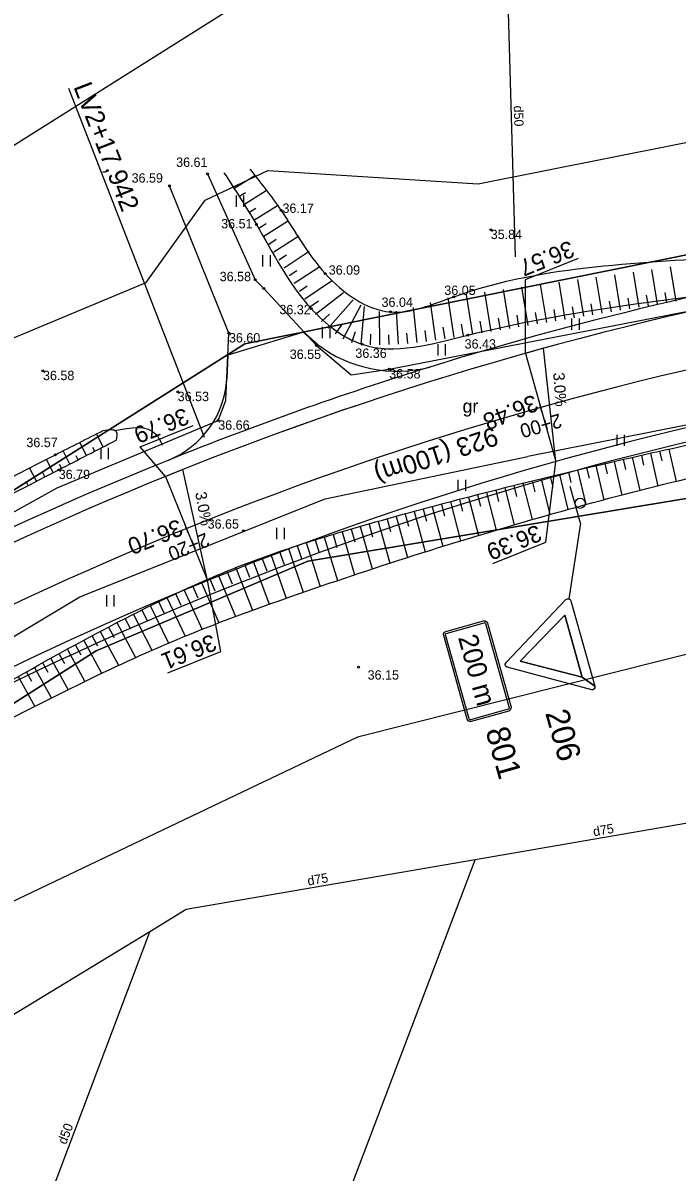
# Model space of a CAD drawing. Extents: x 469981 to 472086, y 246785 to 247785.
# Drawn here: x 471754 to 471788.9, y 247573.1 to 247634.5 of the extents above; entities that cross this region are included whole.
import ezdxf

# ---------------------------------------------------------------- set-up
doc = ezdxf.new("R2010")
doc.units = 0
for name, color, linetype in [('0_923', 7, 'Continuous'), ('0_Asfalta_mala', 7, 'Continuous'), ('0_Asfalta_Nomale', 7, 'Continuous'), ('0_Horiz_aprakst', 7, 'Continuous'), ('0_Ruut_Braukt', 7, 'Continuous'), ('0_Ruut_nomale', 7, 'Continuous'), ('0_Ruutojums_Nobrauktuves_pieslegumi', 7, 'Continuous'), ('0_vertikals', 7, 'Continuous'), ('0_vertkals_cipari', 7, 'Continuous'), ('0_Ziimes', 7, 'Continuous'), ('21', 7, 'Continuous'), ('5_patagas', 7, 'Continuous'), ('6_piketaza', 7, 'Continuous'), ('CELI_CMAL_####_####_#', 7, 'Continuous'), ('CELI_CSEG_####_TKST_#', 7, 'Continuous'), ('DREN_VADP_####_####_#', 7, 'Continuous'), ('DREN_VADP_####_TKST_#', 7, 'Continuous'), ('DREN_VADP_KLKT_####_#', 7, 'Continuous'), ('DREN_VADP_KLKT_TKST_#', 7, 'Continuous'), ('RAMI_UZMR_####_####_#', 7, 'Continuous'), ('RELJ_AATZ_####_TKST_#', 7, 'Continuous'), ('RELJ_ELEM_####_####_#', 7, 'Continuous'), ('RELJ_NOGA_####_####_#', 7, 'Continuous'), ('RELJ_NOGL_####_####_#', 7, 'Continuous'), ('ROBZ_IERR_####_####_#', 7, 'Continuous'), ('ROBZ_PROJ_####_####_#', 7, 'Continuous'), ('TERT_ELEM_####_####_#', 7, 'Continuous'), ('TERT_KONT_####_####_#', 7, 'Continuous')]:
    doc.layers.add(name, color=color, linetype=linetype)

msp = doc.modelspace()

# ---------------------------------------------------------------- linework, layer by layer
at = {"layer": '0_923'}
msp.add_arc((471830.321, 247440.673), 180, 99.00786, 123.42635, dxfattribs=at)
at = {"layer": '0_Asfalta_mala'}
for radius in [183, 177]:
    msp.add_arc((471830.321, 247440.673), radius, 99.00786, 123.42635, dxfattribs=at)
at = {"layer": '0_Asfalta_Nomale'}
for p, q in [((471768.971, 247617.989), (471764.929, 247616.759)), ((471768.971, 247617.989), (471769.697, 247617.337)), ((471764.929, 247616.759), (471764.874, 247615.489))]:
    msp.add_line(p, q, dxfattribs=at)
for centre, radius, start, end in [((471830.321, 247440.673), 183.75, 99.00786, 107.28848), ((471773.95, 247622.896), 7, 232.57724, 284.59006), ((471759.883, 247615.788), 5, 292.12547, 356.58033), ((471830.321, 247440.673), 176.25, 99.00786, 123.42635), ((471830.321, 247440.673), 183.75, 111.90633, 123.42635)]:
    msp.add_arc(centre, radius, start, end, dxfattribs=at)
at = {"layer": '0_Ruut_Braukt'}
for radius in [183, 177]:
    msp.add_arc((471830.321, 247440.673), radius, 99.00786, 123.42635, dxfattribs=at)
at = {"layer": '0_Ruut_nomale'}
for radius, start, end in [(183.75, 99.00786, 107.28848), (183, 99.00801, 123.42635), (183.75, 107.28848, 111.90633), (177, 99.00801, 123.42635), (176.25, 99.00786, 123.42635), (183.75, 111.90633, 123.42635)]:
    msp.add_arc((471830.321, 247440.673), radius, start, end, dxfattribs=at)
at = {"layer": '0_Ruutojums_Nobrauktuves_pieslegumi'}
for p, q in [((471768.971, 247617.989), (471764.929, 247616.759)), ((471769.697, 247617.337), (471768.971, 247617.989)), ((471764.929, 247616.759), (471764.874, 247615.489))]:
    msp.add_line(p, q, dxfattribs=at)
for centre, radius, start, end in [((471773.95, 247622.896), 7, 232.57724, 284.59006), ((471830.321, 247440.673), 183.75, 107.28848, 111.90633), ((471759.883, 247615.788), 5, 292.12547, 356.58033)]:
    msp.add_arc(centre, radius, start, end, dxfattribs=at)
at = {"layer": '0_vertikals'}
for p, q in [((471780.823, 247620.8), (471783.65, 247621.935)), ((471780.819, 247616.851), (471780.823, 247620.8)), ((471760.248, 247611.867), (471763.075, 247613.001)), ((471761.59, 247610.276), (471760.248, 247611.867)), ((471781.907, 247606.764), (471782.442, 247611.075)), ((471779.079, 247605.629), (471781.907, 247606.764)), ((471764.541, 247600.923), (471763.843, 247604.715)), ((471761.713, 247599.788), (471764.541, 247600.923))]:
    msp.add_line(p, q, dxfattribs=at)
for points in [[(471782.442, 247611.075), (471781.783, 247617.12), (471780.819, 247616.851)], [(471763.843, 247604.715), (471762.517, 247610.65), (471761.59, 247610.276)]]:
    msp.add_lwpolyline(points, close=True, dxfattribs=at)
at = {"layer": '0_Ziimes'}
for q in [(471783.2, 247609.739), (471783.134, 247603.747)]:
    msp.add_line((471783.75, 247607.782), q, dxfattribs=at)
for points in [[(471784.487, 247598.932), (471784.417, 247598.89), (471784.354, 247598.885), (471779.847, 247600.089), (471779.756, 247600.153), (471779.731, 247600.253), (471779.782, 247600.351), (471782.977, 247603.699), (471783.009, 247603.726), (471783.037, 247603.741), (471783.053, 247603.747), (471783.134, 247603.747), (471783.202, 247603.709), (471783.244, 247603.639), (471784.524, 247599.083), (471783.846, 247599.568), (471782.918, 247602.871), (471780.537, 247600.42), (471783.846, 247599.568), (471784.524, 247599.083), (471784.525, 247599)], [(471776.583, 247601.891), (471778.612, 247602.461), (471778.64, 247602.462), (471778.662, 247602.449), (471778.675, 247602.424), (471779.938, 247597.93), (471779.938, 247597.898), (471779.923, 247597.872), (471779.899, 247597.856), (471777.883, 247597.29), (471777.853, 247597.29), (471777.829, 247597.306), (471777.813, 247597.333), (471776.55, 247601.83), (471776.55, 247601.858), (471776.563, 247601.879)], [(471780.537, 247600.42), (471782.918, 247602.871), (471783.847, 247599.568)]]:
    msp.add_lwpolyline(points, close=True, dxfattribs=at)
for points in [[(471778.569, 247602.564), (471778.662, 247602.565), (471778.738, 247602.524), (471778.782, 247602.452), (471780.043, 247597.965), (471780.041, 247597.871), (471779.995, 247597.793), (471779.92, 247597.747), (471777.919, 247597.187), (471777.832, 247597.188), (471777.755, 247597.233), (471777.706, 247597.313), (471776.448, 247601.789), (471776.447, 247601.881), (471776.488, 247601.956), (471776.561, 247601.999), (471778.569, 247602.564)], [(471778.612, 247602.461), (471778.64, 247602.462), (471778.662, 247602.449), (471778.675, 247602.424), (471779.938, 247597.93), (471779.938, 247597.898), (471779.923, 247597.872), (471779.899, 247597.856), (471777.883, 247597.29), (471777.853, 247597.29), (471777.829, 247597.306), (471777.813, 247597.333), (471776.55, 247601.83), (471776.55, 247601.858), (471776.563, 247601.879), (471776.583, 247601.891), (471778.612, 247602.461)], [(471782.918, 247602.871), (471783.847, 247599.568), (471780.537, 247600.42), (471782.918, 247602.871)]]:
    msp.add_lwpolyline(points, dxfattribs=at)
msp.add_circle((471783.732, 247608.844), 0.27, dxfattribs=at)
at = {"layer": '21'}
msp.add_arc((471830.321, 247440.673), 180, 99.00786, 123.42635, dxfattribs=at)
at = {"layer": '5_patagas'}
msp.add_lwpolyline([(471763.671, 247612.355), (471756.433, 247631)], dxfattribs=at)
at = {"layer": '6_piketaza'}
for points in [[(471781.698, 247613.722), (471781.563, 247614.204)], [(471762.81, 247607.264), (471762.622, 247607.727)]]:
    msp.add_lwpolyline(points, dxfattribs=at)
at = {"layer": 'CELI_CMAL_####_####_#'}
for points in [[(471763.843, 247626.44), (471766.384, 247620.784), (471766.846, 247620.315), (471769.651, 247617.268), (471771.51, 247615.708), (471773.538, 247616.009), (471793.17, 247619.818), (471820.132, 247624.478), (471843.737, 247629.53), (471860.544, 247633.651)], [(471862.243, 247628.404), (471842.392, 247623.599), (471819.645, 247618.849), (471794.254, 247613.976), (471780.938, 247611.344)], [(471444.29, 247410.189), (471472.037, 247427.783), (471529.617, 247464.738), (471552.455, 247479.724), (471579.938, 247497.81), (471608.708, 247516.399), (471640.167, 247536.853), (471663.898, 247552.17), (471700.29, 247576.588), (471731.688, 247596.287), (471755.809, 247609.67), (471764.411, 247613.273), (471764.823, 247614.335), (471764.981, 247617.933), (471761.802, 247625.793)], [(471701.326, 247547.673), (471701.369, 247550.631), (471701.11, 247563.475), (471701.252, 247565.777), (471702.218, 247568.043), (471703.6, 247570.107), (471733.855, 247589.972), (471757.011, 247603.842), (471770.12, 247609.089), (471780.938, 247611.344)]]:
    msp.add_lwpolyline(points, dxfattribs=at)
at = {"layer": 'DREN_VADP_####_####_#'}
for points in [[(471617.262, 247542.218), (471779.627, 247644.425)], [(471779.627, 247644.425), (471780.269, 247621.999)], [(471769.353, 247566.672), (471778.135, 247589.816)], [(471750.407, 247558.597), (471760.751, 247585.97)]]:
    msp.add_lwpolyline(points, dxfattribs=at)
at = {"layer": 'DREN_VADP_KLKT_####_#'}
msp.add_lwpolyline([(471874.265, 247606.401), (471874.259, 247606.399), (471867.456, 247605.226), (471862.705, 247604.407), (471853.259, 247602.776), (471834.413, 247599.524), (471815.19, 247596.208), (471796.375, 247592.962), (471778.135, 247589.816), (471762.691, 247587.151), (471760.751, 247585.97), (471739.894, 247573.284), (471721.842, 247562.305), (471686.843, 247541.016), (471672.454, 247532.264), (471658.683, 247523.887), (471644.34, 247515.163), (471630.529, 247506.762), (471615.384, 247497.552), (471601.35, 247489.016), (471587.985, 247480.886)], dxfattribs=at)
at = {"layer": 'RAMI_UZMR_####_####_#'}
for points in [[(471355.9, 247363.1), (471457.4, 247429.3), (471524.252, 247472.902), (471743.701, 247613.609), (471760.558, 247620.637), (471763.718, 247625.03), (471767.054, 247626.612), (471778.292, 247625.909), (471806.563, 247631.532), (471842.307, 247641.196)], [(471848.639, 247612.324), (471820.308, 247604.26), (471796.252, 247602.503), (471771.845, 247596.352), (471738.658, 247580.538), (471704.768, 247555.586), (471706.876, 247550.666), (471698.447, 247548.03), (471696.867, 247547.678), (471692.126, 247547.503), (471681.941, 247541.88), (471585.706, 247481.922), (471472.95, 247409.108), (471442.347, 247392.641), (471399.385, 247364.445), (471380.292, 247353.371), (471352.036, 247335.759)]]:
    msp.add_lwpolyline(points, dxfattribs=at)
at = {"layer": 'RELJ_ELEM_####_####_#'}
for centre in [(471763.843, 247626.44), (471761.801, 247625.794), (471767.765, 247624.485), (471766.447, 247623.736), (471778.961, 247623.454), (471766.384, 247620.784), (471770.126, 247621.109), (471766.846, 247620.315), (471776.986, 247619.873), (471769.372, 247619.245), (471773.604, 247619.063), (471764.98, 247617.933), (471777.734, 247617.819), (471769.651, 247617.268), (471772.099, 247617.334), (471755.052, 247615.921), (471773.538, 247616.01), (471762.244, 247614.8), (471764.41, 247613.273), (471755.711, 247611.433), (471755.893, 247610.639), (471765.763, 247607.382), (471771.907, 247600.096)]:
    msp.add_circle(centre, 0.05, dxfattribs=at)
at = {"layer": 'RELJ_NOGA_####_####_#'}
for p, q in [((471764.716, 247626.497), (471764.716, 247626.498)), ((471765.247, 247625.65), (471766.359, 247626.347)), ((471764.981, 247626.074), (471764.982, 247626.074)), ((471765.513, 247625.226), (471765.857, 247625.443)), ((471765.778, 247624.803), (471766.964, 247625.546)), ((471766.044, 247624.379), (471766.411, 247624.609)), ((471766.31, 247623.956), (471767.569, 247624.745)), ((471766.576, 247623.532), (471766.964, 247623.776)), ((471766.842, 247623.109), (471768.159, 247623.943)), ((471767.111, 247622.687), (471767.509, 247622.942)), ((471767.38, 247622.266), (471768.716, 247623.124)), ((471767.651, 247621.846), (471768.053, 247622.105)), ((471767.923, 247621.426), (471769.267, 247622.3)), ((471768.471, 247620.59), (471769.835, 247621.493)), ((471787.872, 247619.472), (471787.568, 247621.33)), ((471788.859, 247619.633), (471788.557, 247621.477)), ((471768.196, 247621.008), (471768.602, 247621.274)), ((471769.026, 247619.758), (471770.454, 247620.718)), ((471783.924, 247618.828), (471783.605, 247620.786)), ((471784.911, 247618.988), (471784.596, 247620.919)), ((471785.898, 247619.149), (471785.588, 247621.052)), ((471786.885, 247619.311), (471786.578, 247621.189)), ((471768.748, 247620.174), (471769.164, 247620.451)), ((471769.596, 247618.937), (471771.092, 247620.095)), ((471778.989, 247618.024), (471778.648, 247620.116)), ((471779.976, 247618.184), (471779.639, 247620.254)), ((471780.963, 247618.345), (471780.63, 247620.387)), ((471781.95, 247618.506), (471781.622, 247620.52)), ((471782.937, 247618.667), (471782.613, 247620.653)), ((471788.365, 247619.553), (471788.275, 247620.108)), ((471769.305, 247619.343), (471769.755, 247619.648)), ((471770.274, 247618.203), (471771.611, 247619.7)), ((471776.026, 247617.556), (471775.75, 247619.574)), ((471777.015, 247617.703), (471776.682, 247619.819)), ((471778.002, 247617.863), (471777.658, 247619.973)), ((471784.418, 247618.908), (471784.323, 247619.491)), ((471785.405, 247619.069), (471785.311, 247619.644)), ((471786.392, 247619.23), (471786.299, 247619.797)), ((471787.378, 247619.391), (471787.287, 247619.951)), ((471769.918, 247618.555), (471770.352, 247618.951)), ((471771.089, 247617.629), (471772.044, 247619.44)), ((471772.039, 247617.338), (471772.226, 247619.35)), ((471773.038, 247617.309), (471773.024, 247619.094)), ((471774.038, 247617.345), (471773.929, 247619.099)), ((471775.034, 247617.432), (471774.836, 247619.3)), ((471780.47, 247618.265), (471780.369, 247618.882)), ((471781.457, 247618.426), (471781.357, 247619.034)), ((471782.444, 247618.586), (471782.346, 247619.186)), ((471783.431, 247618.747), (471783.334, 247619.339)), ((471770.663, 247617.89), (471771.02, 247618.388)), ((471776.521, 247617.627), (471776.427, 247618.251)), ((471777.509, 247617.782), (471777.406, 247618.418)), ((471778.496, 247617.943), (471778.393, 247618.574)), ((471779.483, 247618.104), (471779.381, 247618.728)), ((471771.55, 247617.437), (471771.733, 247618.02)), ((471772.538, 247617.314), (471772.553, 247617.881)), ((471773.538, 247617.32), (471773.52, 247617.841)), ((471774.536, 247617.383), (471774.488, 247617.923)), ((471775.53, 247617.49), (471775.458, 247618.073)), ((471758.264, 247611.851), (471757.909, 247612.546)), ((471756.484, 247610.94), (471756.124, 247611.642)), ((471757.374, 247611.396), (471757.016, 247612.094)), ((471757.819, 247611.623), (471757.712, 247611.832)), ((471758.709, 247612.079), (471758.709, 247612.079)), ((471787.493, 247611.526), (471787.887, 247609.766)), ((471787.981, 247611.635), (471788.098, 247611.11)), ((471788.469, 247611.743), (471788.854, 247610.002)), ((471755.594, 247610.484), (471755.232, 247611.19)), ((471756.039, 247610.712), (471755.93, 247610.924)), ((471756.929, 247611.168), (471756.821, 247611.378)), ((471785.056, 247610.968), (471785.183, 247610.424)), ((471785.543, 247611.081), (471785.96, 247609.28)), ((471786.03, 247611.194), (471786.154, 247610.657)), ((471786.518, 247611.305), (471786.923, 247609.526)), ((471787.005, 247611.416), (471787.125, 247610.885)), ((471754.704, 247610.027), (471754.339, 247610.735)), ((471755.149, 247610.256), (471755.04, 247610.468)), ((471782.138, 247610.272), (471782.277, 247609.704)), ((471782.624, 247610.39), (471783.078, 247608.511)), ((471783.11, 247610.507), (471783.244, 247609.948)), ((471783.596, 247610.624), (471784.039, 247608.773)), ((471784.083, 247610.739), (471784.213, 247610.188)), ((471784.569, 247610.854), (471785, 247609.029)), ((471754.26, 247609.797), (471754.15, 247610.01)), ((471779.712, 247609.669), (471780.21, 247607.698)), ((471780.197, 247609.791), (471780.344, 247609.205)), ((471780.682, 247609.912), (471781.165, 247607.974)), ((471781.167, 247610.033), (471781.31, 247609.456)), ((471781.652, 247610.153), (471782.122, 247608.245)), ((471777.291, 247609.045), (471777.453, 247608.428)), ((471777.775, 247609.171), (471778.305, 247607.133)), ((471778.259, 247609.297), (471778.415, 247608.69)), ((471778.743, 247609.422), (471779.256, 247607.418)), ((471779.227, 247609.545), (471779.379, 247608.949)), ((471775.358, 247608.531), (471775.53, 247607.892)), ((471775.841, 247608.661), (471776.407, 247606.551)), ((471776.324, 247608.789), (471776.491, 247608.162)), ((471776.808, 247608.917), (471777.355, 247606.844)), ((471772.947, 247607.87), (471773.567, 247605.647)), ((471773.429, 247608.004), (471773.612, 247607.343)), ((471773.911, 247608.137), (471774.513, 247605.952)), ((471774.393, 247608.269), (471774.571, 247607.619)), ((471774.876, 247608.4), (471775.457, 247606.253)), ((471771.022, 247607.326), (471771.68, 247605.024)), ((471771.503, 247607.463), (471771.698, 247606.779)), ((471771.984, 247607.6), (471772.624, 247605.338)), ((471772.466, 247607.735), (471772.654, 247607.062)), ((471768.633, 247606.592), (471768.864, 247605.89)), ((471769.108, 247606.747), (471769.858, 247604.408)), ((471769.585, 247606.897), (471769.804, 247606.197)), ((471770.063, 247607.044), (471770.772, 247604.719)), ((471770.542, 247607.187), (471770.746, 247606.492)), ((471767.214, 247606.106), (471768.04, 247603.779)), ((471767.685, 247606.272), (471767.928, 247605.572)), ((471768.159, 247606.434), (471768.951, 247604.096)), ((471765.341, 247605.405), (471766.236, 247603.134)), ((471765.807, 247605.586), (471766.071, 247604.899)), ((471766.274, 247605.763), (471767.138, 247603.459)), ((471766.743, 247605.937), (471766.997, 247605.242)), ((471763.952, 247604.839), (471764.232, 247604.177)), ((471764.413, 247605.032), (471765.337, 247602.801)), ((471764.876, 247605.22), (471765.148, 247604.544)), ((471762.577, 247604.239), (471763.544, 247602.112)), ((471763.034, 247604.443), (471763.32, 247603.796)), ((471763.492, 247604.643), (471764.437, 247602.46)), ((471761.218, 247603.604), (471761.512, 247602.994)), ((471761.669, 247603.82), (471762.644, 247601.751)), ((471762.122, 247604.031), (471762.412, 247603.401)), ((471759.875, 247602.936), (471760.869, 247601.005)), ((471760.321, 247603.163), (471760.618, 247602.572)), ((471760.768, 247603.385), (471761.753, 247601.383)), ((471758.99, 247602.471), (471759.985, 247600.614)), ((471759.431, 247602.705), (471759.729, 247602.137)), ((471757.671, 247601.756), (471757.961, 247601.226)), ((471758.111, 247601.995), (471759.085, 247600.202)), ((471758.55, 247602.233), (471758.847, 247601.687)), ((471756.794, 247601.276), (471757.077, 247600.76)), ((471757.233, 247601.516), (471758.184, 247599.773)), ((471755.479, 247600.555), (471756.397, 247598.886)), ((471755.917, 247600.796), (471756.195, 247600.29)), ((471756.355, 247601.036), (471757.29, 247599.332)), ((471754.603, 247600.072), (471755.505, 247598.439)), ((471755.041, 247600.314), (471755.314, 247599.819)), ((471753.728, 247599.588), (471754.613, 247597.99)), ((471754.165, 247599.831), (471754.433, 247599.346))]:
    msp.add_line(p, q, dxfattribs=at)
for points in [[(471764.716, 247626.497), (471766.448, 247623.736), (471769.372, 247619.245), (471772.099, 247617.333), (471777.734, 247617.819), (471792.871, 247620.291), (471820.146, 247624.816), (471854.894, 247634.06), (471858.623, 247635.133)], [(471706.609, 247571.244), (471711.797, 247574.654), (471722.947, 247581.604), (471728.593, 247584.967), (471734.238, 247588.334), (471740.292, 247591.93), (471746.383, 247595.455), (471752.516, 247598.916), (471758.702, 247602.316), (471764.709, 247605.153), (471767.819, 247606.318), (471770.991, 247607.318), (471782.736, 247610.417), (471794.579, 247613.027), (471800.844, 247614.22), (471807.118, 247615.36), (471813.386, 247616.524), (471819.633, 247617.79), (471842.376, 247622.859), (471856.937, 247625.885), (471859.609, 247626.582), (471862.301, 247626.993)], [(471341.934, 247360.736), (471344.51, 247356.259), (471349.946, 247353.745), (471355.895, 247354.991), (471376.693, 247368.011), (471396.058, 247380.323), (471444.047, 247411.052), (471471.484, 247428.432), (471497.591, 247445.096), (471529.061, 247465.658), (471552.024, 247480.39), (471579.849, 247498.336), (471608.29, 247516.955), (471640.013, 247537.434), (471663.526, 247552.835), (471700.309, 247577.155), (471731.58, 247596.998), (471755.893, 247610.638), (471758.96, 247612.207)]]:
    msp.add_spline(points, degree=3, dxfattribs=at)
at = {"layer": 'RELJ_NOGL_####_####_#'}
for points in [[(471766.101, 247626.689), (471767.766, 247624.484), (471770.126, 247621.109), (471773.604, 247619.063), (471776.986, 247619.873), (471792.111, 247622.064), (471820.66, 247627.746), (471854.033, 247635.856), (471858.41, 247637.011)], [(471707.553, 247570.557), (471712.221, 247573.522), (471723.584, 247580.519), (471729.313, 247583.94), (471735.055, 247587.347), (471740.6, 247590.548), (471746.211, 247593.624), (471751.882, 247596.598), (471757.61, 247599.491), (471762.877, 247601.846), (471768.29, 247603.866), (471781.519, 247608.075), (471794.975, 247611.354), (471801.186, 247612.397), (471807.432, 247613.208), (471813.672, 247614.032), (471819.865, 247615.11), (471825.538, 247616.364), (471831.196, 247617.694), (471836.858, 247619.012), (471842.54, 247620.23), (471859.477, 247623.426), (471861.403, 247623.726)], [(471342.514, 247361.025), (471345.404, 247356.891), (471350.224, 247354.862), (471355.251, 247356.423), (471376.007, 247368.362), (471395.596, 247380.988), (471443.663, 247411.567), (471471.284, 247429.247), (471497.369, 247445.866), (471528.273, 247466.831), (471551.61, 247481.241), (471579.417, 247499.099), (471607.686, 247517.412), (471639.588, 247538.317), (471662.844, 247553.564), (471699.582, 247577.982), (471731.348, 247598.063), (471755.711, 247611.433), (471758.267, 247612.728)], [(471758.267, 247612.728), (471758.966, 247612.684), (471758.96, 247612.207)]]:
    msp.add_spline(points, degree=3, dxfattribs=at)
at = {"layer": 'ROBZ_IERR_####_####_#'}
for points in [[(471848.655, 247680.039), (471863.461, 247637.05), (471765.831, 247617.357), (471524.883, 247464.852), (471503.815, 247507.109)], [(471698.774, 247491.509), (471700.012, 247564.123), (471757.886, 247600.963), (471769.199, 247605.751), (471808.63, 247612.294), (471827.071, 247615.935), (471867.531, 247625.725), (471880.66, 247583.5), (471879.601, 247576.793)]]:
    msp.add_lwpolyline(points, dxfattribs=at)
at = {"layer": 'ROBZ_PROJ_####_####_#'}
msp.add_lwpolyline([(471341.261, 247348.2), (471524.883, 247464.852), (471765.831, 247617.357), (471863.461, 247637.05), (471867.531, 247625.725), (471827.071, 247615.935), (471808.63, 247612.294), (471769.199, 247605.751), (471757.886, 247600.963), (471700.012, 247564.123), (471398.351, 247372.094), (471346.741, 247338.478)], dxfattribs=at)
at = {"layer": 'TERT_ELEM_####_####_#'}
for p, q in [((471765.377, 247624.675), (471765.377, 247625.275)), ((471765.777, 247624.675), (471765.777, 247625.275)), ((471766.797, 247621.49), (471766.797, 247622.09)), ((471767.197, 247621.49), (471767.197, 247622.09)), ((471769.98, 247617.668), (471769.98, 247618.268)), ((471770.38, 247617.668), (471770.38, 247618.268)), ((471783.299, 247618.109), (471783.299, 247618.709)), ((471783.699, 247618.109), (471783.699, 247618.709)), ((471776.15, 247616.737), (471776.15, 247617.337)), ((471776.55, 247616.737), (471776.55, 247617.337)), ((471785.707, 247611.907), (471785.707, 247612.507)), ((471786.107, 247611.907), (471786.107, 247612.507)), ((471758.157, 247611.2), (471758.157, 247611.8)), ((471758.557, 247611.2), (471758.557, 247611.8)), ((471777.224, 247609.506), (471777.224, 247610.106)), ((471777.624, 247609.506), (471777.624, 247610.106)), ((471767.541, 247606.933), (471767.541, 247607.533)), ((471767.941, 247606.933), (471767.941, 247607.533)), ((471758.457, 247603.332), (471758.457, 247603.932)), ((471758.857, 247603.332), (471758.857, 247603.932))]:
    msp.add_line(p, q, dxfattribs=at)
at = {"layer": 'TERT_KONT_####_####_#'}
msp.add_spline([(471758.866, 247612.736), (471761.077, 247612.544), (471761.42, 247611.956)], degree=3, dxfattribs=at)

# ---------------------------------------------------------------- texts
at = {"layer": '0_Horiz_aprakst'}
msp.add_text('923 (100m)', height=1, rotation=198.28465, dxfattribs=at).set_placement((471779.143, 247612.939))
at = {"layer": '0_vertkals_cipari'}
for s, height, rotation, p in [('36.57', 0.9, 201.85903, (471783.188, 247622.898)), ('3.0%', 0.5993, 273.83485, (471782.298, 247615.813)), ('36.48', 0.9, 201.85903, (471781.252, 247614.675)), ('36.79', 0.9, 201.85903, (471762.613, 247613.965)), ('3.0%', 0.5993, 280.20105, (471763.174, 247609.408)), ('36.70', 0.9, 201.85903, (471762.279, 247608.025)), ('36.39', 0.9, 201.85903, (471781.445, 247607.727)), ('36.61', 0.9, 201.85903, (471764.079, 247601.886))]:
    msp.add_text(s, height=height, rotation=rotation, dxfattribs=at).set_placement(p)
at = {"layer": '0_Ziimes'}
for s, height, rotation, p in [('200 m', 1.045, 285.69192, (471777.207, 247601.681)), ('206', 1.25, 285.69412, (471781.863, 247597.653)), ('801', 1.25, 285.69412, (471778.672, 247596.713))]:
    msp.add_text(s, height=height, rotation=rotation, dxfattribs=at).set_placement(p)
at = {"layer": '5_patagas'}
msp.add_text('LV2+17,942', height=1, rotation=291.2171, dxfattribs=at).set_placement((471756.666, 247631.09))
at = {"layer": '6_piketaza'}
for s, rotation, p in [('2+00', 195.69412, (471782.628, 247613.646)), ('2+20', 202.06032, (471763.742, 247607.291))]:
    msp.add_text(s, height=0.75, rotation=rotation, dxfattribs=at).set_placement(p)
at = {"layer": 'CELI_CSEG_####_TKST_#'}
msp.add_text('gr', height=0.7, dxfattribs=at).set_placement((471777.459, 247613.684))
at = {"layer": 'DREN_VADP_####_TKST_#'}
for rotation, p in [(271.63946, (471780.188, 247630.075)), (69.29858, (471756.284, 247574.573))]:
    msp.add_text('d50', height=0.5, rotation=rotation, dxfattribs=at).set_placement(p)
at = {"layer": 'DREN_VADP_KLKT_TKST_#'}
for rotation, p in [(9.78842, (471784.469, 247591.061)), (9.78724, (471769.215, 247588.429))]:
    msp.add_text('d75', height=0.5, rotation=rotation, dxfattribs=at).set_placement(p)
at = {"layer": 'RELJ_AATZ_####_TKST_#'}
for s, p in [('36.61', (471762.161, 247626.808)), ('36.59', (471759.783, 247625.966)), ('36.17', (471767.841, 247624.352)), ('36.51', (471764.567, 247623.524)), ('35.84', (471778.961, 247622.954)), ('36.09', (471770.309, 247621.053)), ('36.58', (471764.488, 247620.704)), ('36.05', (471776.482, 247619.97)), ('36.04', (471773.13, 247619.332)), ('36.32', (471767.675, 247618.939)), ('36.60', (471764.98, 247617.433)), ('36.55', (471768.229, 247616.554)), ('36.36', (471771.732, 247616.609)), ('36.43', (471777.566, 247617.105)), ('36.58', (471755.052, 247615.421)), ('36.58', (471773.538, 247615.51)), ('36.53', (471762.244, 247614.3)), ('36.66', (471764.41, 247612.773)), ('36.57', (471754.165, 247611.843)), ('36.79', (471755.893, 247610.139)), ('36.65', (471763.843, 247607.491)), ('36.15', (471772.387, 247599.429))]:
    msp.add_text(s, height=0.5, dxfattribs=at).set_placement(p)

doc.saveas('drawing.dxf')
